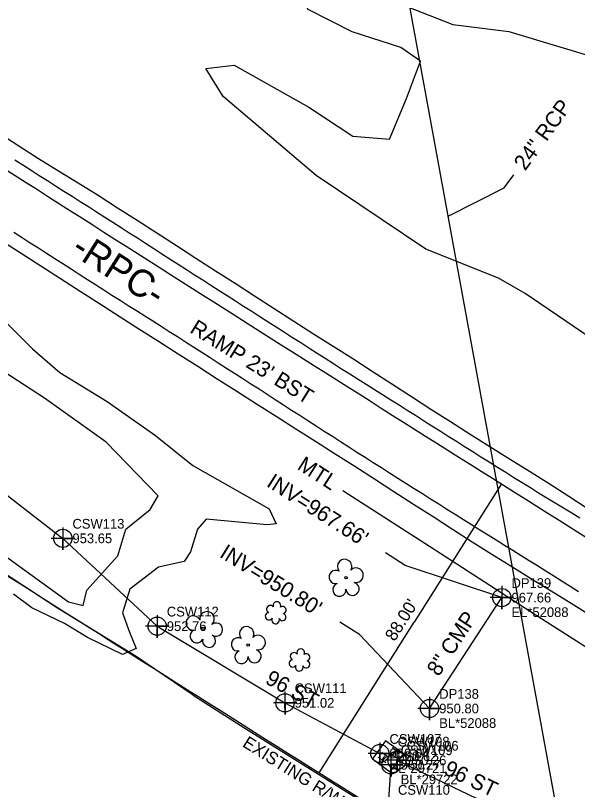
# Model space of a CAD drawing. Extents: x 1182322 to 1186765, y 572295 to 575411.
# Drawn here: x 1184083.8 to 1184228.5, y 573854 to 574053.4 of the extents above; entities that cross this region are included whole.
import ezdxf

# ---------------------------------------------------------------- set-up
doc = ezdxf.new("R2010")
doc.units = 0
for name, color, linetype in [('COGO Default Chain', 7, 'Continuous'), ('Exist Guardrail', 7, 'Continuous'), ('Exist Guardrail Text', 7, 'Continuous'), ('Exist Horizontal Alignment', 7, 'Continuous'), ('Exist Horizontal Alignment Direction Label', 7, 'Continuous'), ('Exist Other Culture Fence Line', 7, 'Continuous'), ('Exist Right of Way Line', 7, 'Continuous'), ('Exist Right of Way Line Text', 7, 'Continuous'), ('Exist Right of Way Width CELL', 7, 'Continuous'), ('Exist Roads EOP', 7, 'Continuous'), ('Exist Roads EOP Text', 7, 'Continuous'), ('Exist Roads EOT', 7, 'Continuous'), ('Exist Structure Minor Pipes CMP 8 Inch', 7, 'Continuous'), ('Exist Structure Minor Pipes CMP 8 Inch Cogo Comment', 7, 'Continuous'), ('Exist Structure Minor Pipes CMP 8 Inch Cogo Elevation', 7, 'Continuous'), ('Exist Structure Minor Pipes CMP 8 Inch Cogo Number', 7, 'Continuous'), ('Exist Structure Minor Pipes CMP 8 Inch Cogo Point CELL', 7, 'Continuous'), ('Exist Structure Minor Pipes CMP 8 Inch Invert', 7, 'Continuous'), ('Exist Structure Minor Pipes CMP 8 Inch Leader', 7, 'Continuous'), ('Exist Structure Minor Pipes CMP 8 Inch Text', 7, 'Continuous'), ('Exist Structure Minor Pipes RCP 24 Inch', 7, 'Continuous'), ('Exist Structure Minor Pipes RCP 24 Inch Leader', 7, 'Continuous'), ('Exist Structure Minor Pipes RCP 24 Inch Text', 7, 'Continuous'), ('Exist Utilities Telephone Hand Hole CELL', 7, 'Continuous'), ('Exist Utilities Telephone Hand Hole Cogo Elevation', 7, 'Continuous'), ('Exist Utilities Telephone Hand Hole Cogo Number', 7, 'Continuous'), ('Exist Utilities Telephone UG Conduit SUE LOS B', 7, 'Continuous'), ('Exist Utilities Telephone UG Conduit SUE LOS B Cogo Comment', 7, 'Continuous'), ('Exist Utilities Telephone UG Conduit SUE LOS B Cogo Elevation', 7, 'Continuous'), ('Exist Utilities Telephone UG Conduit SUE LOS B Cogo Number', 7, 'Continuous'), ('Exist Utilities Telephone UG Conduit SUE LOS B Cogo Point CELL', 7, 'Continuous'), ('Exist Utilities Telephone UG Conduit SUE LOS B Text', 7, 'Continuous'), ('Exist Vegetation Shrub CELL', 7, 'Continuous'), ('Exist Vegetation Tree CELL', 7, 'Continuous'), ('Exist Vegetation Woods Line', 7, 'Continuous')]:
    doc.layers.add(name, color=color, linetype=linetype)

msp = doc.modelspace()

# ---------------------------------------------------------------- linework, layer by layer
at = {"layer": 'COGO Default Chain'}
msp.add_arc((1195941.73, 592569.89), 22022.71, 237.351741, 237.915207, dxfattribs=at)
at = {"layer": 'Exist Guardrail'}
msp.add_lwpolyline([(1184110.33, 573506.92), (1184130.54, 573534.34), (1184155.27, 573568.07), (1184186.68, 573611.03), (1184216.05, 573651.34), (1184250.31, 573698.26), (1184296.53, 573761.98), (1184304.74, 573774.22), (1184309.5, 573782.03), (1184314.68, 573793.24), (1184315.95, 573797.84), (1184316.69, 573804.7), (1184316.43, 573809.21), (1184314.08, 573817.02), (1184312.23, 573821.63), (1184307.47, 573830.27), (1184301.17, 573839.67), (1184294.78, 573847.1), (1184289.35, 573852.18), (1184272.59, 573863.91), (1184251.29, 573877.57), (1184217.33, 573899.26), (1184190.41, 573916.67), (1184168.05, 573930.98)], dxfattribs=at)
at = {"layer": 'Exist Horizontal Alignment'}
msp.add_arc((1195941.73, 592569.89), 22022.71, 237.351741, 237.915207, dxfattribs=at)
at = {"layer": 'Exist Other Culture Fence Line'}
for points in [[(1184129.53, 573878.39), (1184114.9, 573888.31), (1184094.64, 573900.8), (1184058.94, 573923.99), (1183975.11, 573977.38), (1183956.27, 573990.02)], [(1184129.53, 573878.39), (1184142.55, 573870.04), (1184177.6, 573848.11), (1184205.83, 573829.88), (1184239.24, 573807.93), (1184260.72, 573794.32), (1184269.26, 573788.27)]]:
    msp.add_lwpolyline(points, dxfattribs=at)
at = {"layer": 'Exist Right of Way Line'}
msp.add_arc((1195941.73, 592569.89), 22110.71, 237.351741, 237.915207, dxfattribs=at)
at = {"layer": 'Exist Right of Way Width CELL'}
for p in [(1184208.91, 573932.82), (1184162.03, 573858.34)]:
    msp.add_line(p, (1184186.46, 573897.16), dxfattribs=at)
at = {"layer": 'Exist Roads EOP'}
for points in [[(1184079.62, 574023.03), (1184084.68, 574019.82), (1184089.74, 574016.61), (1184094.84, 574013.45), (1184099.96, 574010.33), (1184105.04, 574007.16), (1184110.09, 574003.91), (1184115.13, 574000.67), (1184120.18, 573997.43), (1184125.22, 573994.19), (1184130.26, 573990.94), (1184135.3, 573987.69), (1184140.33, 573984.44), (1184145.37, 573981.19), (1184150.41, 573977.94), (1184155.44, 573974.69), (1184160.5, 573971.47), (1184165.56, 573968.25), (1184170.62, 573965.04), (1184175.67, 573961.82), (1184180.72, 573958.58), (1184185.74, 573955.31), (1184190.78, 573952.06), (1184195.84, 573948.84), (1184200.89, 573945.61), (1184205.96, 573942.41), (1184211.05, 573939.24), (1184216.13, 573936.06), (1184221.22, 573932.88), (1184226.26, 573929.63), (1184231.29, 573926.37)], [(1184231.96, 573898.78), (1184226.87, 573901.95), (1184221.78, 573905.11), (1184216.69, 573908.27), (1184211.59, 573911.43), (1184206.5, 573914.59), (1184201.41, 573917.76), (1184196.36, 573921), (1184191.33, 573924.25), (1184186.29, 573927.5), (1184181.25, 573930.75), (1184176.22, 573934), (1184171.17, 573937.24), (1184166.11, 573940.46), (1184161.05, 573943.67), (1184155.99, 573946.89), (1184150.93, 573950.11), (1184145.88, 573953.32), (1184140.82, 573956.54), (1184135.76, 573959.76), (1184130.71, 573962.98), (1184125.65, 573966.2), (1184120.6, 573969.43), (1184115.55, 573972.66), (1184110.5, 573975.9), (1184105.45, 573979.13), (1184100.41, 573982.37), (1184095.36, 573985.61), (1184090.31, 573988.84), (1184085.27, 573992.08), (1184080.22, 573995.32)]]:
    msp.add_lwpolyline(points, dxfattribs=at)
at = {"layer": 'Exist Roads EOT'}
for points in [[(1184083.6, 574016.27), (1184085.7, 574014.92), (1184087.81, 574013.58), (1184089.91, 574012.23), (1184092.02, 574010.89), (1184094.12, 574009.55), (1184096.23, 574008.21), (1184098.34, 574006.87), (1184100.45, 574005.53), (1184102.56, 574004.19), (1184104.67, 574002.85), (1184106.78, 574001.51), (1184108.89, 574000.18), (1184111, 573998.83), (1184113.09, 573997.48), (1184115.19, 573996.12), (1184117.29, 573994.77), (1184119.39, 573993.41), (1184121.49, 573992.06), (1184123.59, 573990.7), (1184125.69, 573989.35), (1184127.79, 573988.01), (1184129.9, 573986.66), (1184132, 573985.32), (1184134.11, 573983.97), (1184136.21, 573982.63), (1184138.32, 573981.28), (1184140.42, 573979.94), (1184142.53, 573978.59), (1184144.63, 573977.25), (1184146.73, 573975.9), (1184148.84, 573974.55), (1184150.94, 573973.21), (1184153.05, 573971.86), (1184155.15, 573970.52), (1184157.26, 573969.17), (1184159.36, 573967.83), (1184161.47, 573966.48), (1184163.57, 573965.14), (1184165.68, 573963.79), (1184167.78, 573962.45), (1184169.89, 573961.11), (1184172, 573959.77), (1184174.11, 573958.44), (1184176.23, 573957.11), (1184178.34, 573955.78), (1184180.46, 573954.45), (1184182.57, 573953.12), (1184184.68, 573951.79), (1184186.79, 573950.45), (1184188.9, 573949.11), (1184191.01, 573947.77), (1184193.12, 573946.43), (1184195.23, 573945.09), (1184197.33, 573943.75), (1184199.44, 573942.41), (1184201.56, 573941.08), (1184203.67, 573939.76), (1184205.79, 573938.43), (1184207.91, 573937.11), (1184210.03, 573935.78), (1184212.15, 573934.46), (1184214.27, 573933.13), (1184216.39, 573931.82), (1184218.52, 573930.51), (1184220.65, 573929.21), (1184222.78, 573927.9), (1184224.91, 573926.6), (1184227.04, 573925.3), (1184229.17, 573923.99)], [(1184228.77, 573904.97), (1184226.67, 573906.31), (1184224.56, 573907.65), (1184222.45, 573908.99), (1184220.33, 573910.31), (1184218.21, 573911.63), (1184216.09, 573912.96), (1184213.98, 573914.28), (1184211.86, 573915.6), (1184209.74, 573916.93), (1184207.62, 573918.25), (1184205.5, 573919.57), (1184203.38, 573920.89), (1184201.26, 573922.21), (1184199.14, 573923.54), (1184197.03, 573924.87), (1184194.91, 573926.2), (1184192.8, 573927.53), (1184190.68, 573928.86), (1184188.57, 573930.19), (1184186.46, 573931.52), (1184184.35, 573932.86), (1184182.24, 573934.19), (1184180.13, 573935.53), (1184178.02, 573936.87), (1184175.91, 573938.21), (1184173.8, 573939.55), (1184171.69, 573940.89), (1184169.59, 573942.24), (1184167.49, 573943.59), (1184165.39, 573944.94), (1184163.29, 573946.29), (1184161.19, 573947.64), (1184159.09, 573949), (1184156.99, 573950.36), (1184154.9, 573951.71), (1184152.8, 573953.07), (1184150.7, 573954.43), (1184148.61, 573955.79), (1184146.5, 573957.14), (1184144.4, 573958.49), (1184142.3, 573959.84), (1184140.2, 573961.19), (1184138.1, 573962.54), (1184135.99, 573963.89), (1184133.89, 573965.23), (1184131.79, 573966.58), (1184129.68, 573967.93), (1184127.58, 573969.28), (1184125.48, 573970.63), (1184123.38, 573971.97), (1184121.27, 573973.32), (1184119.16, 573974.66), (1184117.05, 573975.99), (1184114.94, 573977.33), (1184112.83, 573978.66), (1184110.72, 573980), (1184108.61, 573981.34), (1184106.51, 573982.69), (1184104.4, 573984.03), (1184102.3, 573985.38), (1184100.19, 573986.72), (1184098.09, 573988.07), (1184095.99, 573989.42), (1184093.88, 573990.77), (1184091.78, 573992.12), (1184089.68, 573993.47), (1184087.58, 573994.81), (1184085.47, 573996.16), (1184083.36, 573997.5)]]:
    msp.add_lwpolyline(points, dxfattribs=at)
at = {"layer": 'Exist Structure Minor Pipes CMP 8 Inch'}
msp.add_line((1184190.41, 573874.92), (1184209.03, 573903.48), dxfattribs=at)
at = {"layer": 'Exist Structure Minor Pipes CMP 8 Inch Cogo Point CELL'}
for points in [[(1184209.03, 573906.48), (1184209.03, 573900.48), (1184209.03, 573903.48), (1184212.03, 573903.48), (1184206.03, 573903.48)], [(1184190.41, 573877.92), (1184190.41, 573871.92), (1184190.41, 573874.92), (1184193.41, 573874.92), (1184187.41, 573874.92)]]:
    msp.add_lwpolyline(points, dxfattribs=at)
for centre in [(1184209.03, 573903.48), (1184190.41, 573874.92)]:
    msp.add_circle(centre, 2.34, dxfattribs=at)
at = {"layer": 'Exist Structure Minor Pipes CMP 8 Inch Leader'}
for points in [[(1184209.03, 573903.48), (1184184.18, 573911.79), (1184179.11, 573915.01)], [(1184190.41, 573874.92), (1184172.38, 573893.96), (1184167.28, 573897.12)]]:
    msp.add_lwpolyline(points, dxfattribs=at)
at = {"layer": 'Exist Structure Minor Pipes RCP 24 Inch'}
msp.add_line((1184225.16, 573838.41), (1184182.34, 574071.98), dxfattribs=at)
at = {"layer": 'Exist Structure Minor Pipes RCP 24 Inch Leader'}
msp.add_lwpolyline([(1184195.21, 574001.72), (1184209.67, 574009.05), (1184212.12, 574012.42)], dxfattribs=at)
at = {"layer": 'Exist Utilities Telephone Hand Hole CELL'}
for p, q in [((1184179.06, 573866.62), (1184175.69, 573861.99)), ((1184183.69, 573863.24), (1184179.06, 573866.62)), ((1184179.69, 573862.62), (1184179.69, 573862.62)), ((1184180.32, 573858.62), (1184183.69, 573863.24)), ((1184175.69, 573861.99), (1184180.32, 573858.62))]:
    msp.add_line(p, q, dxfattribs=at)
at = {"layer": 'Exist Utilities Telephone UG Conduit SUE LOS B'}
for points in [[(1183184.2, 574290.24), (1183230.46, 574277.8), (1183276.74, 574264.86), (1183322.88, 574252.13), (1183369.36, 574239.84), (1183416.41, 574227.82), (1183461.9, 574217.61), (1183507.97, 574205.1), (1183555.78, 574190.97), (1183600.29, 574174.7), (1183642.38, 574158.78), (1183685.83, 574141.54), (1183729.44, 574124.53), (1183772.61, 574105.48), (1183815.48, 574084.72), (1183856.9, 574064.89), (1183910.26, 574040.72), (1183938.65, 574025.64), (1184017.13, 573974.93), (1184056.25, 573949.51), (1184095.95, 573918.75), (1184120.25, 573896.12), (1184153.18, 573876.37), (1184177.6, 573863.32)], [(1184180.49, 573860.41), (1184179.78, 573850.2), (1184170.42, 573827.95), (1184167.72, 573814.64), (1184178.81, 573799.47)], [(1184182.02, 573861.57), (1184218.73, 573844), (1184250.56, 573829.18), (1184284.14, 573810.22), (1184301.94, 573798.27), (1184322.33, 573794.9)]]:
    msp.add_lwpolyline(points, dxfattribs=at)
at = {"layer": 'Exist Utilities Telephone UG Conduit SUE LOS B Cogo Point CELL'}
for points in [[(1184095.94, 573921.57), (1184095.97, 573915.75), (1184095.95, 573918.75), (1184098.97, 573918.75), (1184092.97, 573918.75)], [(1184120.23, 573898.93), (1184120.27, 573893.12), (1184120.25, 573896.12), (1184123.27, 573896.12), (1184117.27, 573896.12)], [(1184153.17, 573879.19), (1184153.2, 573873.37), (1184153.18, 573876.37), (1184156.2, 573876.37), (1184150.2, 573876.37)], [(1184177.58, 573866.14), (1184177.62, 573860.32), (1184177.6, 573863.32), (1184180.62, 573863.32), (1184174.62, 573863.32)], [(1184182, 573864.38), (1184182.04, 573858.57), (1184182.02, 573861.57), (1184185.04, 573861.57), (1184179.04, 573861.57)], [(1184180.47, 573863.22), (1184180.5, 573857.41), (1184180.49, 573860.41), (1184183.5, 573860.41), (1184177.5, 573860.41)]]:
    msp.add_lwpolyline(points, dxfattribs=at)
for centre in [(1184095.97, 573918.75), (1184120.27, 573896.12), (1184153.2, 573876.37), (1184177.62, 573863.32), (1184180.5, 573860.41), (1184182.04, 573861.57)]:
    msp.add_circle(centre, 2.34, dxfattribs=at)
at = {"layer": 'Exist Vegetation Shrub CELL'}
for p, q in [((1184150.87, 573899.4), (1184150.87, 573899.4)), ((1184157.01, 573887.23), (1184157.01, 573887.23))]:
    msp.add_line(p, q, dxfattribs=at)
for centre, radius, start, end in [((1184151.1, 573901.44), 0.99, 334.8391, 200.4717), ((1184149.39, 573900.52), 0.968, 35.8908, 245.4216), ((1184152.55, 573900.26), 0.929, 284.4567, 126.0861), ((1184149.07, 573898.69), 0.955, 95.1099, 327.9534), ((1184150.75, 573897.71), 0.984, 151.2797, 21.387), ((1184152.51, 573898.47), 0.937, 204.9913, 73.4601), ((1184157.24, 573889.27), 0.99, 334.8391, 200.4717), ((1184155.53, 573888.36), 0.968, 35.8908, 245.4216), ((1184158.68, 573888.1), 0.929, 284.4567, 126.0861), ((1184155.21, 573886.52), 0.955, 95.1099, 327.9534), ((1184158.65, 573886.3), 0.937, 204.9913, 73.4601), ((1184156.88, 573885.54), 0.984, 151.2797, 21.387)]:
    msp.add_arc(centre, radius, start, end, dxfattribs=at)
at = {"layer": 'Exist Vegetation Tree CELL'}
for p, q in [((1184168.92, 573908.63), (1184168.92, 573908.63)), ((1184132.1, 573895.57), (1184132.1, 573895.57)), ((1184143.69, 573891.29), (1184143.69, 573891.29))]:
    msp.add_line(p, q, dxfattribs=at)
for centre in [(1184168.92, 573908.63), (1184132.1, 573895.57), (1184143.69, 573891.29)]:
    msp.add_circle(centre, 0.326, dxfattribs=at)
for centre, radius, start, end in [((1184168.54, 573911.5), 1.86, 330.1651, 219.7134), ((1184166.31, 573908.79), 1.73, 62.6636, 279.3457), ((1184171.47, 573909.22), 1.9, 257.1011, 134.1999), ((1184167.22, 573905.51), 1.69, 111.5671, 6.231), ((1184170.59, 573905.73), 1.7, 181.2822, 74.56), ((1184129.54, 573896.93), 1.86, 24.5374, 274.0857), ((1184133.11, 573897.98), 1.9, 311.4735, 188.5723), ((1184135.43, 573895.24), 1.7, 235.6545, 128.9324), ((1184130.46, 573893.54), 1.73, 117.036, 333.7181), ((1184143.31, 573894.16), 1.86, 330.1651, 219.7134), ((1184133.64, 573892.36), 1.69, 165.9394, 60.6034), ((1184141.09, 573891.44), 1.73, 62.6636, 279.3457), ((1184146.24, 573891.88), 1.9, 257.1011, 134.1999), ((1184141.99, 573888.17), 1.69, 111.5671, 6.231), ((1184145.37, 573888.39), 1.7, 181.2822, 74.56)]:
    msp.add_arc(centre, radius, start, end, dxfattribs=at)
at = {"layer": 'Exist Vegetation Woods Line'}
for points in [[(1184208.17, 573985.74), (1184189.48, 573993.28), (1184161.23, 574012.19), (1184137.23, 574032.58), (1184132.79, 574039.76), (1184140.09, 574040.66), (1184159.33, 574029.79), (1184170.64, 574022.36), (1184180.07, 574021.59), (1184184.48, 574032.01), (1184188.08, 574041.67), (1184183, 574045.18), (1184170.47, 574049.24), (1184159.13, 574054.97), (1184154.38, 574063.57), (1184156.91, 574072.67), (1184164.55, 574076.64), (1184170.89, 574071.57), (1184177.84, 574060.46), (1184182.61, 574056.51), (1184196.45, 574051.12), (1184210.86, 574049.31), (1184246.83, 574038.51)], [(1184246.83, 574038.51), (1184260.08, 574033.62), (1184269.81, 574025.68), (1184272.92, 574017.91), (1184277.6, 574013.35), (1184280.24, 574010.98), (1184288.56, 574008.15), (1184299.97, 574011.29), (1184307.92, 574011.62), (1184331.29, 574005.23), (1184335.04, 574000.38), (1184327.52, 573942.16), (1184320.86, 573929.83), (1184313.27, 573925.64), (1184300.6, 573928.45), (1184254.54, 573954.95), (1184215.02, 573981.83), (1184208.17, 573985.74)], [(1184081.45, 573974.29), (1184088.2, 573967.55), (1184095.23, 573961.48), (1184107.36, 573954.02), (1184119.81, 573945.26), (1184129.49, 573937.49), (1184149.13, 573926.35), (1184150.9, 573922.51), (1184148.58, 573922.25), (1184132.91, 573923.69), (1184130.68, 573921.09), (1184128.82, 573915.24), (1184127.18, 573912.82), (1184120.59, 573911.29), (1184113.19, 573905.65), (1184111.32, 573899.6), (1184113.16, 573894.55), (1184114.84, 573890.35), (1184111.33, 573888.84), (1184102.31, 573893.24), (1184096.37, 573896.8), (1184088.01, 573900.83), (1184083.28, 573904.35)], [(1184081.21, 573914.19), (1184097.46, 573902.41), (1184101.19, 573901.43), (1184102.18, 573905.38), (1184110.11, 573914.21), (1184112.19, 573921.07), (1184118.49, 573926.14), (1184120.54, 573929.73), (1184107.11, 573943.51), (1184091.28, 573954.86), (1184077.46, 573963.8)]]:
    msp.add_lwpolyline(points, dxfattribs=at)

# ---------------------------------------------------------------- texts
at = {"layer": 'Exist Guardrail Text'}
msp.add_text('MTL', height=4, rotation=327.3804, dxfattribs=at).set_placement((1184156.09, 573936.73))
at = {"layer": 'Exist Horizontal Alignment Direction Label'}
msp.add_text('-RPC-', height=7, rotation=327.5022, dxfattribs=at).set_placement((1184097.7, 573992.13))
at = {"layer": 'Exist Right of Way Line Text'}
msp.add_text('EXISTING R/W', height=3.2, rotation=327.7956, dxfattribs=at).set_placement((1184142.02, 573865.28))
at = {"layer": 'Exist Right of Way Width CELL'}
msp.add_text("88.00'", height=3.2, rotation=57.8079, dxfattribs=at).set_placement((1184181.43, 573892.02))
at = {"layer": 'Exist Roads EOP Text'}
msp.add_text("RAMP 23' BST", height=4, rotation=328.2763, dxfattribs=at).set_placement((1184128.43, 573971.94))
at = {"layer": 'Exist Structure Minor Pipes CMP 8 Inch Cogo Comment'}
for s, p in [('EL*52088', (1184211.53, 573898.48)), ('BL*52088', (1184192.91, 573869.92))]:
    msp.add_text(s, height=2.5, dxfattribs=at).set_placement(p)
at = {"layer": 'Exist Structure Minor Pipes CMP 8 Inch Cogo Elevation'}
for s, p in [('967.66', (1184211.53, 573902.23)), ('950.80', (1184192.91, 573873.67))]:
    msp.add_text(s, height=2.5, dxfattribs=at).set_placement(p)
at = {"layer": 'Exist Structure Minor Pipes CMP 8 Inch Cogo Number'}
for s, p in [('DP139', (1184211.53, 573905.98)), ('DP138', (1184192.91, 573877.42))]:
    msp.add_text(s, height=2.5, dxfattribs=at).set_placement(p)
at = {"layer": 'Exist Structure Minor Pipes CMP 8 Inch Invert'}
for s, rotation, p in [("INV=967.66'", 327.5452, (1184148.18, 573932.31)), ("INV=950.80'", 328.2315, (1184136.09, 573914.08))]:
    msp.add_text(s, height=4, rotation=rotation, dxfattribs=at).set_placement(p)
at = {"layer": 'Exist Structure Minor Pipes CMP 8 Inch Text'}
msp.add_text('8" CMP', height=4, rotation=56.9006, dxfattribs=at).set_placement((1184192.79, 573882.97))
at = {"layer": 'Exist Structure Minor Pipes RCP 24 Inch Text'}
msp.add_text('24" RCP', height=4, rotation=54.0262, dxfattribs=at).set_placement((1184215.05, 574013.25))
at = {"layer": 'Exist Utilities Telephone Hand Hole CELL'}
for p in [(1184181.64, 573861.8), (1184178.94, 573860.58)]:
    msp.add_text('H', height=2.5, rotation=53.9157, dxfattribs=at).set_placement(p)
at = {"layer": 'Exist Utilities Telephone Hand Hole Cogo Elevation'}
msp.add_text('950.62', height=2.5, dxfattribs=at).set_placement((1184182.19, 573861.37))
at = {"layer": 'Exist Utilities Telephone Hand Hole Cogo Number'}
msp.add_text('CSW108', height=2.5, dxfattribs=at).set_placement((1184182.19, 573865.12))
at = {"layer": 'Exist Utilities Telephone UG Conduit SUE LOS B Cogo Comment'}
for s, p in [('BL*29721', (1184180.1, 573858.32)), ('BL*29722', (1184182.99, 573855.41))]:
    msp.add_text(s, height=2.5, dxfattribs=at).set_placement(p)
at = {"layer": 'Exist Utilities Telephone UG Conduit SUE LOS B Cogo Elevation'}
for s, p in [('953.65', (1184098.45, 573917.5)), ('952.76', (1184122.75, 573894.87)), ('951.02', (1184155.68, 573875.12)), ('950.64', (1184180.1, 573862.07)), ('950.26', (1184184.52, 573860.32)), ('950.27', (1184182.99, 573859.16))]:
    msp.add_text(s, height=2.5, dxfattribs=at).set_placement(p)
at = {"layer": 'Exist Utilities Telephone UG Conduit SUE LOS B Cogo Number'}
for s, p in [('CSW113', (1184098.45, 573921.25)), ('CSW112', (1184122.75, 573898.62)), ('CSW111', (1184155.68, 573878.87)), ('CSW107', (1184180.1, 573865.82)), ('CSW106', (1184184.52, 573864.07)), ('CSW109', (1184182.99, 573862.91)), ('CSW110', (1184182.28, 573852.7))]:
    msp.add_text(s, height=2.5, dxfattribs=at).set_placement(p)
at = {"layer": 'Exist Utilities Telephone UG Conduit SUE LOS B Text'}
for rotation, p in [(331.8703, (1184147.83, 573881.5)), (334.4242, (1184193.81, 573858.14))]:
    msp.add_text('96 ST', height=4, rotation=rotation, dxfattribs=at).set_placement(p)

doc.saveas('drawing.dxf')
